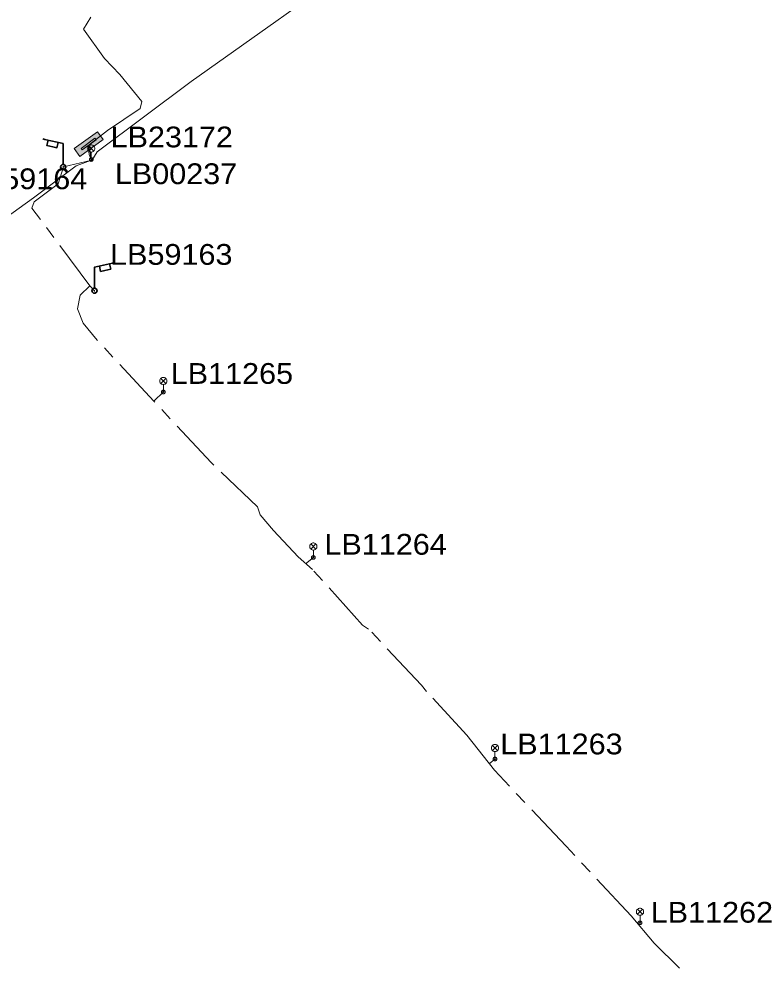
# Model space of a CAD drawing. Extents: x -688049 to -687261, y -973611 to -973038.
# Drawn here: x -687759.7 to -687682.8, y -973580.7 to -973481.6 of the extents above; entities that cross this region are included whole.
import ezdxf

# ---------------------------------------------------------------- set-up
doc = ezdxf.new("R2010")
doc.units = 0
doc.header["$LTSCALE"] = 0.87
doc.linetypes.add('LONG_DASH_SHORT_DASH', pattern=[9.9, 6, -1.2, 1.5, -1.2])
doc.layers.add('1', color=7, linetype='Continuous', lineweight=13)

msp = doc.modelspace()

# ---------------------------------------------------------------- hatches: boundary and pattern name
at = {"layer": '1'}
for points in [[(-687750.892, -973494.181), (-687753.318, -973495.945), (-687753.906, -973495.137), (-687751.48, -973493.372)], [(-687751.612, -973494.21), (-687753.068, -973495.269), (-687753.186, -973495.107), (-687751.73, -973494.049)]]:
    msp.add_hatch(color=256, dxfattribs=at).paths.add_polyline_path(points)

# ---------------------------------------------------------------- linework, layer by layer
at = {"layer": '1', "linetype": 'LONG_DASH_SHORT_DASH'}
for p, q in [((-687752.34, -973494.74), (-687752.12, -973496.27)), ((-687752.28, -973509.45), (-687751.79, -973509.96)), ((-687752.28, -973509.45), (-687751.79, -973509.96)), ((-687752.28, -973509.45), (-687751.79, -973509.96)), ((-687752.28, -973509.45), (-687751.79, -973509.96)), ((-687752.28, -973509.45), (-687751.79, -973509.96)), ((-687752.28, -973509.45), (-687751.79, -973509.96)), ((-687745.6, -973521.48), (-687744.6, -973520.53)), ((-687745.6, -973521.48), (-687744.6, -973520.53)), ((-687745.6, -973521.48), (-687744.6, -973520.53)), ((-687745.6, -973521.48), (-687744.6, -973520.53)), ((-687745.6, -973521.48), (-687744.6, -973520.53)), ((-687745.6, -973521.48), (-687744.6, -973520.53)), ((-687745.6, -973521.48), (-687744.6, -973520.53)), ((-687745.6, -973521.48), (-687744.6, -973520.53)), ((-687729.758, -973538.48), (-687728.94, -973537.8)), ((-687729.758, -973538.48), (-687728.94, -973537.8)), ((-687729.758, -973538.48), (-687728.94, -973537.8)), ((-687729.758, -973538.48), (-687728.94, -973537.8)), ((-687729.758, -973538.48), (-687728.94, -973537.8)), ((-687729.758, -973538.48), (-687728.94, -973537.8)), ((-687729.758, -973538.48), (-687728.94, -973537.8)), ((-687729.758, -973538.48), (-687728.94, -973537.8)), ((-687710, -973558.84), (-687710.606, -973559.339)), ((-687710, -973558.84), (-687710.606, -973559.339)), ((-687710, -973558.84), (-687710.606, -973559.339)), ((-687710, -973558.84), (-687710.606, -973559.339)), ((-687710, -973558.84), (-687710.606, -973559.339)), ((-687710, -973558.84), (-687710.606, -973559.339)), ((-687710, -973558.84), (-687710.606, -973559.339)), ((-687710, -973558.84), (-687710.606, -973559.339))]:
    msp.add_line(p, q, dxfattribs=at)
at = {"layer": '1'}
for p, q in [((-687752.385, -973494.855), (-687751.855, -973495.385)), ((-687752.385, -973495.385), (-687751.855, -973494.855)), ((-687752.12, -973496.27), (-687752.12, -973495.495)), ((-687744.865, -973519.115), (-687744.335, -973519.645)), ((-687744.865, -973519.645), (-687744.335, -973519.115)), ((-687744.6, -973520.53), (-687744.6, -973519.755)), ((-687729.214, -973536.392), (-687728.684, -973536.922)), ((-687729.214, -973536.922), (-687728.684, -973536.392)), ((-687728.949, -973537.807), (-687728.949, -973537.032)), ((-687710.265, -973557.425), (-687709.735, -973557.955)), ((-687710.265, -973557.955), (-687709.735, -973557.425)), ((-687710, -973558.84), (-687710, -973558.065)), ((-687695.135, -973574.515), (-687694.605, -973575.045)), ((-687695.135, -973575.045), (-687694.605, -973574.515)), ((-687694.87, -973575.93), (-687694.87, -973575.155))]:
    msp.add_line(p, q, dxfattribs=at)
at = {"layer": '1', "lineweight": 35}
for p, q in [((-687755.027, -973497.05), (-687755.081, -973497.05)), ((-687751.817, -973509.96), (-687751.763, -973509.96))]:
    msp.add_line(p, q, dxfattribs=at)
at = {"layer": '1'}
for points in [[(-687721.92, -973474.37), (-687722.962, -973474.805), (-687741.711, -973488.143), (-687751.504, -973495.468), (-687752.07, -973496.37)], [(-687752.34, -973494.74), (-687752.421, -973495.195), (-687752.354, -973495.735), (-687752.12, -973496.27)], [(-687752.105, -973496.355), (-687753.681, -973496.941), (-687758.146, -973500.27), (-687778.62, -973515.036), (-687779.16, -973515.94)]]:
    msp.add_lwpolyline(points, dxfattribs=at)
at = {"layer": '1', "linetype": 'LONG_DASH_SHORT_DASH'}
for points in [[(-687752.18, -973481.4), (-687752.93, -973482.67), (-687750.74, -973485.73), (-687749.13, -973487.38), (-687746.86, -973490.22), (-687747.02, -973490.93), (-687750.43, -973493.25), (-687752.29, -973494.69), (-687752.34, -973494.74)], [(-687752.28, -973509.45), (-687758.31, -973501.34), (-687758.07, -973500.67), (-687755.58, -973498.8), (-687755, -973497.05), (-687752.07, -973496.33)], [(-687752.28, -973509.45), (-687758.31, -973501.34), (-687758.07, -973500.67), (-687755.58, -973498.8), (-687755, -973497.05), (-687752.07, -973496.33)], [(-687752.28, -973509.45), (-687758.31, -973501.34), (-687758.07, -973500.67), (-687755.58, -973498.8), (-687755, -973497.05), (-687752.07, -973496.33)], [(-687752.28, -973509.45), (-687758.31, -973501.34), (-687758.07, -973500.67), (-687755.58, -973498.8), (-687755, -973497.05), (-687752.07, -973496.33)], [(-687752.28, -973509.45), (-687758.31, -973501.34), (-687758.07, -973500.67), (-687755.58, -973498.8), (-687755, -973497.05), (-687752.07, -973496.33)], [(-687752.28, -973509.45), (-687758.31, -973501.34), (-687758.07, -973500.67), (-687755.58, -973498.8), (-687755, -973497.05), (-687752.07, -973496.33)], [(-687752.28, -973509.45), (-687758.31, -973501.34), (-687758.07, -973500.67), (-687755.58, -973498.8), (-687755, -973497.05), (-687752.07, -973496.33)], [(-687752.28, -973509.45), (-687758.31, -973501.34), (-687758.07, -973500.67), (-687755.58, -973498.8), (-687755, -973497.05), (-687752.07, -973496.33)], [(-687745.6, -973521.48), (-687751.5, -973515.11), (-687752.95, -973513.36), (-687753.55, -973511.86), (-687753.29, -973510.44), (-687752.28, -973509.45)], [(-687745.6, -973521.48), (-687751.5, -973515.11), (-687752.95, -973513.36), (-687753.55, -973511.86), (-687753.29, -973510.44), (-687752.28, -973509.45)], [(-687745.6, -973521.48), (-687751.5, -973515.11), (-687752.95, -973513.36), (-687753.55, -973511.86), (-687753.29, -973510.44), (-687752.28, -973509.45)], [(-687745.6, -973521.48), (-687751.5, -973515.11), (-687752.95, -973513.36), (-687753.55, -973511.86), (-687753.29, -973510.44), (-687752.28, -973509.45)], [(-687745.6, -973521.48), (-687751.5, -973515.11), (-687752.95, -973513.36), (-687753.55, -973511.86), (-687753.29, -973510.44), (-687752.28, -973509.45)], [(-687745.6, -973521.48), (-687751.5, -973515.11), (-687752.95, -973513.36), (-687753.55, -973511.86), (-687753.29, -973510.44), (-687752.28, -973509.45), (-687751.79, -973509.96)], [(-687745.6, -973521.48), (-687751.5, -973515.11), (-687752.95, -973513.36), (-687753.55, -973511.86), (-687753.29, -973510.44), (-687752.28, -973509.45), (-687751.79, -973509.96)], [(-687745.6, -973521.48), (-687751.5, -973515.11), (-687752.95, -973513.36), (-687753.55, -973511.86), (-687753.29, -973510.44), (-687752.28, -973509.45)], [(-687690.76, -973580.65), (-687693.4, -973578.05), (-687695.8, -973575.19), (-687702.58, -973567.93), (-687710.06, -973560), (-687712.94, -973556.34), (-687717.13, -973551.8), (-687717.67, -973551.13), (-687723.18, -973545.27), (-687723.81, -973544.86), (-687729.04, -973539.07), (-687730.55, -973537.74), (-687733.09, -973534.98), (-687734.5, -973533.36), (-687734.79, -973532.51), (-687739.61, -973527.9), (-687745.6, -973521.48)], [(-687690.76, -973580.65), (-687693.4, -973578.05), (-687695.8, -973575.19), (-687702.58, -973567.93), (-687710.06, -973560), (-687712.94, -973556.34), (-687717.13, -973551.8), (-687717.67, -973551.13), (-687723.18, -973545.27), (-687723.81, -973544.86), (-687729.04, -973539.07), (-687730.55, -973537.74), (-687733.09, -973534.98), (-687734.5, -973533.36), (-687734.79, -973532.51), (-687739.61, -973527.9), (-687745.6, -973521.48)], [(-687690.76, -973580.65), (-687693.4, -973578.05), (-687695.8, -973575.19), (-687702.58, -973567.93), (-687710.06, -973560), (-687712.94, -973556.34), (-687717.13, -973551.8), (-687717.67, -973551.13), (-687723.18, -973545.27), (-687723.81, -973544.86), (-687729.04, -973539.07), (-687730.55, -973537.74), (-687733.09, -973534.98), (-687734.5, -973533.36), (-687734.79, -973532.51), (-687739.61, -973527.9), (-687745.6, -973521.48)], [(-687690.76, -973580.65), (-687693.4, -973578.05), (-687695.8, -973575.19), (-687702.58, -973567.93), (-687710.06, -973560), (-687712.94, -973556.34), (-687717.13, -973551.8), (-687717.67, -973551.13), (-687723.18, -973545.27), (-687723.81, -973544.86), (-687729.04, -973539.07), (-687730.55, -973537.74), (-687733.09, -973534.98), (-687734.5, -973533.36), (-687734.79, -973532.51), (-687739.61, -973527.9), (-687745.6, -973521.48)], [(-687690.76, -973580.65), (-687693.4, -973578.05), (-687695.8, -973575.19), (-687702.58, -973567.93), (-687710.06, -973560), (-687712.94, -973556.34), (-687717.13, -973551.8), (-687717.67, -973551.13), (-687723.18, -973545.27), (-687723.81, -973544.86), (-687729.04, -973539.07), (-687730.55, -973537.74), (-687733.09, -973534.98), (-687734.5, -973533.36), (-687734.79, -973532.51), (-687739.61, -973527.9), (-687745.6, -973521.48)], [(-687690.76, -973580.65), (-687693.4, -973578.05), (-687695.8, -973575.19), (-687702.58, -973567.93), (-687710.06, -973560), (-687712.94, -973556.34), (-687717.13, -973551.8), (-687717.67, -973551.13), (-687723.18, -973545.27), (-687723.81, -973544.86), (-687729.04, -973539.07), (-687730.55, -973537.74), (-687733.09, -973534.98), (-687734.5, -973533.36), (-687734.79, -973532.51), (-687739.61, -973527.9), (-687745.6, -973521.48)], [(-687690.76, -973580.65), (-687693.4, -973578.05), (-687695.8, -973575.19), (-687702.58, -973567.93), (-687710.06, -973560), (-687712.94, -973556.34), (-687717.13, -973551.8), (-687717.67, -973551.13), (-687723.18, -973545.27), (-687723.81, -973544.86), (-687729.04, -973539.07), (-687730.55, -973537.74), (-687733.09, -973534.98), (-687734.5, -973533.36), (-687734.79, -973532.51), (-687739.61, -973527.9), (-687745.6, -973521.48)], [(-687690.76, -973580.65), (-687693.4, -973578.05), (-687695.8, -973575.19), (-687702.58, -973567.93), (-687710.06, -973560), (-687712.94, -973556.34), (-687717.13, -973551.8), (-687717.67, -973551.13), (-687723.18, -973545.27), (-687723.81, -973544.86), (-687729.04, -973539.07), (-687730.55, -973537.74), (-687733.09, -973534.98), (-687734.5, -973533.36), (-687734.79, -973532.51), (-687739.61, -973527.9), (-687745.6, -973521.48)]]:
    msp.add_lwpolyline(points, dxfattribs=at)
at = {"layer": '1'}
for points in [[(-687750.892, -973494.181), (-687753.318, -973495.945), (-687753.906, -973495.137), (-687751.48, -973493.372)], [(-687750.892, -973494.181), (-687753.318, -973495.945), (-687753.906, -973495.137), (-687751.48, -973493.372)], [(-687751.612, -973494.21), (-687753.068, -973495.269), (-687753.186, -973495.107), (-687751.73, -973494.049)], [(-687751.745, -973495.12), (-687751.751, -973495.055), (-687751.768, -973494.992), (-687751.795, -973494.932), (-687751.833, -973494.879), (-687751.879, -973494.833), (-687751.932, -973494.795), (-687751.992, -973494.768), (-687752.055, -973494.751), (-687752.12, -973494.745), (-687752.185, -973494.751), (-687752.248, -973494.768), (-687752.308, -973494.795), (-687752.361, -973494.833), (-687752.407, -973494.879), (-687752.445, -973494.932), (-687752.472, -973494.992), (-687752.489, -973495.055), (-687752.495, -973495.12), (-687752.489, -973495.185), (-687752.472, -973495.248), (-687752.445, -973495.308), (-687752.407, -973495.361), (-687752.361, -973495.407), (-687752.308, -973495.445), (-687752.248, -973495.472), (-687752.185, -973495.489), (-687752.12, -973495.495), (-687752.055, -973495.489), (-687751.992, -973495.472), (-687751.932, -973495.445), (-687751.879, -973495.407), (-687751.833, -973495.361), (-687751.795, -973495.308), (-687751.768, -973495.248), (-687751.751, -973495.185)], [(-687751.93, -973496.27), (-687751.933, -973496.237), (-687751.941, -973496.205), (-687751.955, -973496.175), (-687751.974, -973496.148), (-687751.998, -973496.124), (-687752.025, -973496.105), (-687752.055, -973496.091), (-687752.087, -973496.083), (-687752.12, -973496.08), (-687752.153, -973496.083), (-687752.185, -973496.091), (-687752.215, -973496.105), (-687752.242, -973496.124), (-687752.266, -973496.148), (-687752.285, -973496.175), (-687752.299, -973496.205), (-687752.307, -973496.237), (-687752.31, -973496.27), (-687752.307, -973496.303), (-687752.299, -973496.335), (-687752.285, -973496.365), (-687752.266, -973496.392), (-687752.242, -973496.416), (-687752.215, -973496.435), (-687752.185, -973496.449), (-687752.153, -973496.457), (-687752.12, -973496.46), (-687752.087, -973496.457), (-687752.055, -973496.449), (-687752.025, -973496.435), (-687751.998, -973496.416), (-687751.974, -973496.392), (-687751.955, -973496.365), (-687751.941, -973496.335), (-687751.933, -973496.303)], [(-687752.07, -973496.27), (-687752.071, -973496.261), (-687752.073, -973496.253), (-687752.077, -973496.245), (-687752.082, -973496.238), (-687752.088, -973496.232), (-687752.095, -973496.227), (-687752.103, -973496.223), (-687752.111, -973496.221), (-687752.12, -973496.22), (-687752.129, -973496.221), (-687752.137, -973496.223), (-687752.145, -973496.227), (-687752.152, -973496.232), (-687752.158, -973496.238), (-687752.163, -973496.245), (-687752.167, -973496.253), (-687752.169, -973496.261), (-687752.17, -973496.27), (-687752.169, -973496.279), (-687752.167, -973496.287), (-687752.163, -973496.295), (-687752.158, -973496.302), (-687752.152, -973496.308), (-687752.145, -973496.313), (-687752.137, -973496.317), (-687752.129, -973496.319), (-687752.12, -973496.32), (-687752.111, -973496.319), (-687752.103, -973496.317), (-687752.095, -973496.313), (-687752.088, -973496.308), (-687752.082, -973496.302), (-687752.077, -973496.295), (-687752.073, -973496.287), (-687752.071, -973496.279)], [(-687744.225, -973519.38), (-687744.231, -973519.315), (-687744.248, -973519.252), (-687744.275, -973519.192), (-687744.313, -973519.139), (-687744.359, -973519.093), (-687744.412, -973519.055), (-687744.472, -973519.028), (-687744.535, -973519.011), (-687744.6, -973519.005), (-687744.665, -973519.011), (-687744.728, -973519.028), (-687744.788, -973519.055), (-687744.841, -973519.093), (-687744.887, -973519.139), (-687744.925, -973519.192), (-687744.952, -973519.252), (-687744.969, -973519.315), (-687744.975, -973519.38), (-687744.969, -973519.445), (-687744.952, -973519.508), (-687744.925, -973519.568), (-687744.887, -973519.621), (-687744.841, -973519.667), (-687744.788, -973519.705), (-687744.728, -973519.732), (-687744.665, -973519.749), (-687744.6, -973519.755), (-687744.535, -973519.749), (-687744.472, -973519.732), (-687744.412, -973519.705), (-687744.359, -973519.667), (-687744.313, -973519.621), (-687744.275, -973519.568), (-687744.248, -973519.508), (-687744.231, -973519.445)], [(-687744.41, -973520.53), (-687744.413, -973520.497), (-687744.421, -973520.465), (-687744.435, -973520.435), (-687744.454, -973520.408), (-687744.478, -973520.384), (-687744.505, -973520.365), (-687744.535, -973520.351), (-687744.567, -973520.343), (-687744.6, -973520.34), (-687744.633, -973520.343), (-687744.665, -973520.351), (-687744.695, -973520.365), (-687744.722, -973520.384), (-687744.746, -973520.408), (-687744.765, -973520.435), (-687744.779, -973520.465), (-687744.787, -973520.497), (-687744.79, -973520.53), (-687744.787, -973520.563), (-687744.779, -973520.595), (-687744.765, -973520.625), (-687744.746, -973520.652), (-687744.722, -973520.676), (-687744.695, -973520.695), (-687744.665, -973520.709), (-687744.633, -973520.717), (-687744.6, -973520.72), (-687744.567, -973520.717), (-687744.535, -973520.709), (-687744.505, -973520.695), (-687744.478, -973520.676), (-687744.454, -973520.652), (-687744.435, -973520.625), (-687744.421, -973520.595), (-687744.413, -973520.563)], [(-687744.55, -973520.53), (-687744.551, -973520.521), (-687744.553, -973520.513), (-687744.557, -973520.505), (-687744.562, -973520.498), (-687744.568, -973520.492), (-687744.575, -973520.487), (-687744.583, -973520.483), (-687744.591, -973520.481), (-687744.6, -973520.48), (-687744.609, -973520.481), (-687744.617, -973520.483), (-687744.625, -973520.487), (-687744.632, -973520.492), (-687744.638, -973520.498), (-687744.643, -973520.505), (-687744.647, -973520.513), (-687744.649, -973520.521), (-687744.65, -973520.53), (-687744.649, -973520.539), (-687744.647, -973520.547), (-687744.643, -973520.555), (-687744.638, -973520.562), (-687744.632, -973520.568), (-687744.625, -973520.573), (-687744.617, -973520.577), (-687744.609, -973520.579), (-687744.6, -973520.58), (-687744.591, -973520.579), (-687744.583, -973520.577), (-687744.575, -973520.573), (-687744.568, -973520.568), (-687744.562, -973520.562), (-687744.557, -973520.555), (-687744.553, -973520.547), (-687744.551, -973520.539)], [(-687728.574, -973536.657), (-687728.58, -973536.592), (-687728.597, -973536.529), (-687728.624, -973536.47), (-687728.662, -973536.416), (-687728.708, -973536.37), (-687728.762, -973536.332), (-687728.821, -973536.305), (-687728.884, -973536.288), (-687728.949, -973536.282), (-687729.014, -973536.288), (-687729.077, -973536.305), (-687729.136, -973536.332), (-687729.19, -973536.37), (-687729.236, -973536.416), (-687729.274, -973536.47), (-687729.301, -973536.529), (-687729.318, -973536.592), (-687729.324, -973536.657), (-687729.318, -973536.722), (-687729.301, -973536.785), (-687729.274, -973536.845), (-687729.236, -973536.898), (-687729.19, -973536.944), (-687729.136, -973536.982), (-687729.077, -973537.009), (-687729.014, -973537.026), (-687728.949, -973537.032), (-687728.884, -973537.026), (-687728.821, -973537.009), (-687728.762, -973536.982), (-687728.708, -973536.944), (-687728.662, -973536.898), (-687728.624, -973536.845), (-687728.597, -973536.785), (-687728.58, -973536.722)], [(-687728.759, -973537.807), (-687728.762, -973537.774), (-687728.77, -973537.742), (-687728.784, -973537.712), (-687728.803, -973537.685), (-687728.827, -973537.661), (-687728.854, -973537.642), (-687728.884, -973537.628), (-687728.916, -973537.62), (-687728.949, -973537.617), (-687728.982, -973537.62), (-687729.014, -973537.628), (-687729.044, -973537.642), (-687729.071, -973537.661), (-687729.095, -973537.685), (-687729.114, -973537.712), (-687729.128, -973537.742), (-687729.136, -973537.774), (-687729.139, -973537.807), (-687729.136, -973537.84), (-687729.128, -973537.872), (-687729.114, -973537.902), (-687729.095, -973537.929), (-687729.071, -973537.953), (-687729.044, -973537.972), (-687729.014, -973537.986), (-687728.982, -973537.994), (-687728.949, -973537.997), (-687728.916, -973537.994), (-687728.884, -973537.986), (-687728.854, -973537.972), (-687728.827, -973537.953), (-687728.803, -973537.929), (-687728.784, -973537.902), (-687728.77, -973537.872), (-687728.762, -973537.84)], [(-687728.899, -973537.807), (-687728.9, -973537.798), (-687728.902, -973537.79), (-687728.906, -973537.782), (-687728.911, -973537.775), (-687728.917, -973537.769), (-687728.924, -973537.764), (-687728.932, -973537.76), (-687728.94, -973537.758), (-687728.949, -973537.757), (-687728.958, -973537.758), (-687728.966, -973537.76), (-687728.974, -973537.764), (-687728.981, -973537.769), (-687728.987, -973537.775), (-687728.992, -973537.782), (-687728.996, -973537.79), (-687728.998, -973537.798), (-687728.999, -973537.807), (-687728.998, -973537.816), (-687728.996, -973537.824), (-687728.992, -973537.832), (-687728.987, -973537.839), (-687728.981, -973537.845), (-687728.974, -973537.85), (-687728.966, -973537.854), (-687728.958, -973537.856), (-687728.949, -973537.857), (-687728.94, -973537.856), (-687728.932, -973537.854), (-687728.924, -973537.85), (-687728.917, -973537.845), (-687728.911, -973537.839), (-687728.906, -973537.832), (-687728.902, -973537.824), (-687728.9, -973537.816)], [(-687709.625, -973557.69), (-687709.631, -973557.625), (-687709.648, -973557.562), (-687709.675, -973557.503), (-687709.713, -973557.449), (-687709.759, -973557.403), (-687709.812, -973557.365), (-687709.872, -973557.338), (-687709.935, -973557.321), (-687710, -973557.315), (-687710.065, -973557.321), (-687710.128, -973557.338), (-687710.188, -973557.365), (-687710.241, -973557.403), (-687710.287, -973557.449), (-687710.325, -973557.503), (-687710.352, -973557.562), (-687710.369, -973557.625), (-687710.375, -973557.69), (-687710.369, -973557.755), (-687710.352, -973557.818), (-687710.325, -973557.878), (-687710.287, -973557.931), (-687710.241, -973557.977), (-687710.188, -973558.015), (-687710.128, -973558.042), (-687710.065, -973558.059), (-687710, -973558.065), (-687709.935, -973558.059), (-687709.872, -973558.042), (-687709.812, -973558.015), (-687709.759, -973557.977), (-687709.713, -973557.931), (-687709.675, -973557.878), (-687709.648, -973557.818), (-687709.631, -973557.755)], [(-687709.81, -973558.84), (-687709.813, -973558.807), (-687709.821, -973558.775), (-687709.835, -973558.745), (-687709.854, -973558.718), (-687709.878, -973558.694), (-687709.905, -973558.675), (-687709.935, -973558.661), (-687709.967, -973558.653), (-687710, -973558.65), (-687710.033, -973558.653), (-687710.065, -973558.661), (-687710.095, -973558.675), (-687710.122, -973558.694), (-687710.146, -973558.718), (-687710.165, -973558.745), (-687710.179, -973558.775), (-687710.187, -973558.807), (-687710.19, -973558.84), (-687710.187, -973558.873), (-687710.179, -973558.905), (-687710.165, -973558.935), (-687710.146, -973558.962), (-687710.122, -973558.986), (-687710.095, -973559.005), (-687710.065, -973559.019), (-687710.033, -973559.027), (-687710, -973559.03), (-687709.967, -973559.027), (-687709.935, -973559.019), (-687709.905, -973559.005), (-687709.878, -973558.986), (-687709.854, -973558.962), (-687709.835, -973558.935), (-687709.821, -973558.905), (-687709.813, -973558.873)], [(-687709.95, -973558.84), (-687709.951, -973558.831), (-687709.953, -973558.823), (-687709.957, -973558.815), (-687709.962, -973558.808), (-687709.968, -973558.802), (-687709.975, -973558.797), (-687709.983, -973558.793), (-687709.991, -973558.791), (-687710, -973558.79), (-687710.009, -973558.791), (-687710.017, -973558.793), (-687710.025, -973558.797), (-687710.032, -973558.802), (-687710.038, -973558.808), (-687710.043, -973558.815), (-687710.047, -973558.823), (-687710.049, -973558.831), (-687710.05, -973558.84), (-687710.049, -973558.849), (-687710.047, -973558.857), (-687710.043, -973558.865), (-687710.038, -973558.872), (-687710.032, -973558.878), (-687710.025, -973558.883), (-687710.017, -973558.887), (-687710.009, -973558.889), (-687710, -973558.89), (-687709.991, -973558.889), (-687709.983, -973558.887), (-687709.975, -973558.883), (-687709.968, -973558.878), (-687709.962, -973558.872), (-687709.957, -973558.865), (-687709.953, -973558.857), (-687709.951, -973558.849)], [(-687694.495, -973574.78), (-687694.501, -973574.715), (-687694.518, -973574.652), (-687694.545, -973574.592), (-687694.583, -973574.539), (-687694.629, -973574.493), (-687694.682, -973574.455), (-687694.742, -973574.428), (-687694.805, -973574.411), (-687694.87, -973574.405), (-687694.935, -973574.411), (-687694.998, -973574.428), (-687695.058, -973574.455), (-687695.111, -973574.493), (-687695.157, -973574.539), (-687695.195, -973574.592), (-687695.222, -973574.652), (-687695.239, -973574.715), (-687695.245, -973574.78), (-687695.239, -973574.845), (-687695.222, -973574.908), (-687695.195, -973574.968), (-687695.157, -973575.021), (-687695.111, -973575.067), (-687695.058, -973575.105), (-687694.998, -973575.132), (-687694.935, -973575.149), (-687694.87, -973575.155), (-687694.805, -973575.149), (-687694.742, -973575.132), (-687694.682, -973575.105), (-687694.629, -973575.067), (-687694.583, -973575.021), (-687694.545, -973574.968), (-687694.518, -973574.908), (-687694.501, -973574.845)], [(-687694.68, -973575.93), (-687694.683, -973575.897), (-687694.691, -973575.865), (-687694.705, -973575.835), (-687694.724, -973575.808), (-687694.748, -973575.784), (-687694.775, -973575.765), (-687694.805, -973575.751), (-687694.837, -973575.743), (-687694.87, -973575.74), (-687694.903, -973575.743), (-687694.935, -973575.751), (-687694.965, -973575.765), (-687694.992, -973575.784), (-687695.016, -973575.808), (-687695.035, -973575.835), (-687695.049, -973575.865), (-687695.057, -973575.897), (-687695.06, -973575.93), (-687695.057, -973575.963), (-687695.049, -973575.995), (-687695.035, -973576.025), (-687695.016, -973576.052), (-687694.992, -973576.076), (-687694.965, -973576.095), (-687694.935, -973576.109), (-687694.903, -973576.117), (-687694.87, -973576.12), (-687694.837, -973576.117), (-687694.805, -973576.109), (-687694.775, -973576.095), (-687694.748, -973576.076), (-687694.724, -973576.052), (-687694.705, -973576.025), (-687694.691, -973575.995), (-687694.683, -973575.963)], [(-687694.82, -973575.93), (-687694.821, -973575.921), (-687694.823, -973575.913), (-687694.827, -973575.905), (-687694.832, -973575.898), (-687694.838, -973575.892), (-687694.845, -973575.887), (-687694.853, -973575.883), (-687694.861, -973575.881), (-687694.87, -973575.88), (-687694.879, -973575.881), (-687694.887, -973575.883), (-687694.895, -973575.887), (-687694.902, -973575.892), (-687694.908, -973575.898), (-687694.913, -973575.905), (-687694.917, -973575.913), (-687694.919, -973575.921), (-687694.92, -973575.93), (-687694.919, -973575.939), (-687694.917, -973575.947), (-687694.913, -973575.955), (-687694.908, -973575.962), (-687694.902, -973575.968), (-687694.895, -973575.973), (-687694.887, -973575.977), (-687694.879, -973575.979), (-687694.87, -973575.98), (-687694.861, -973575.979), (-687694.853, -973575.977), (-687694.845, -973575.973), (-687694.838, -973575.968), (-687694.832, -973575.962), (-687694.827, -973575.955), (-687694.823, -973575.947), (-687694.821, -973575.939)]]:
    msp.add_lwpolyline(points, close=True, dxfattribs=at)
at = {"layer": '1', "lineweight": 35}
for points in [[(-687755.054, -973496.795), (-687755.141, -973496.795), (-687755.276, -973496.893), (-687755.33, -973497.05), (-687755.276, -973497.207), (-687755.141, -973497.305), (-687754.973, -973497.305), (-687754.837, -973497.207), (-687754.783, -973497.05), (-687754.837, -973496.893), (-687754.973, -973496.795), (-687755.054, -973496.795), (-687755.054, -973496.107), (-687755.054, -973495.419), (-687755.054, -973494.731), (-687755.054, -973494.612), (-687755.688, -973494.465), (-687756.322, -973494.319), (-687756.956, -973494.173), (-687757.167, -973494.124)], [(-687756.625, -973494.259), (-687756.761, -973494.801), (-687756.127, -973494.948), (-687755.704, -973495.045), (-687755.569, -973494.503)], [(-687751.79, -973509.705), (-687751.703, -973509.705), (-687751.568, -973509.803), (-687751.514, -973509.96), (-687751.568, -973510.117), (-687751.703, -973510.215), (-687751.871, -973510.215), (-687752.007, -973510.117), (-687752.061, -973509.96), (-687752.007, -973509.803), (-687751.871, -973509.705), (-687751.79, -973509.705), (-687751.79, -973509.017), (-687751.79, -973508.329), (-687751.79, -973507.641), (-687751.79, -973507.522), (-687751.156, -973507.375), (-687750.522, -973507.229), (-687749.888, -973507.083), (-687749.677, -973507.034)], [(-687750.219, -973507.169), (-687750.083, -973507.711), (-687750.717, -973507.858), (-687751.14, -973507.955), (-687751.275, -973507.413)]]:
    msp.add_lwpolyline(points, dxfattribs=at)

# ---------------------------------------------------------------- texts
at = {"layer": '1', "width": 1.1}
for s, height, p in [('LB23172', 2.168, (-687750.106, -973495.002)), ('LB00237', 2.167, (-687749.657, -973498.838)), ('LB59164', 2.168, (-687765.306, -973499.365)), ('LB59163', 2.168, (-687750.156, -973507.258)), ('LB11265', 2.168, (-687743.832, -973519.684)), ('LB11264', 2.168, (-687727.796, -973537.513)), ('LB11263', 2.168, (-687709.452, -973558.352)), ('LB11262', 2.168, (-687693.756, -973575.917))]:
    msp.add_text(s, height=height, dxfattribs=at).set_placement(p)

doc.saveas('drawing.dxf')
